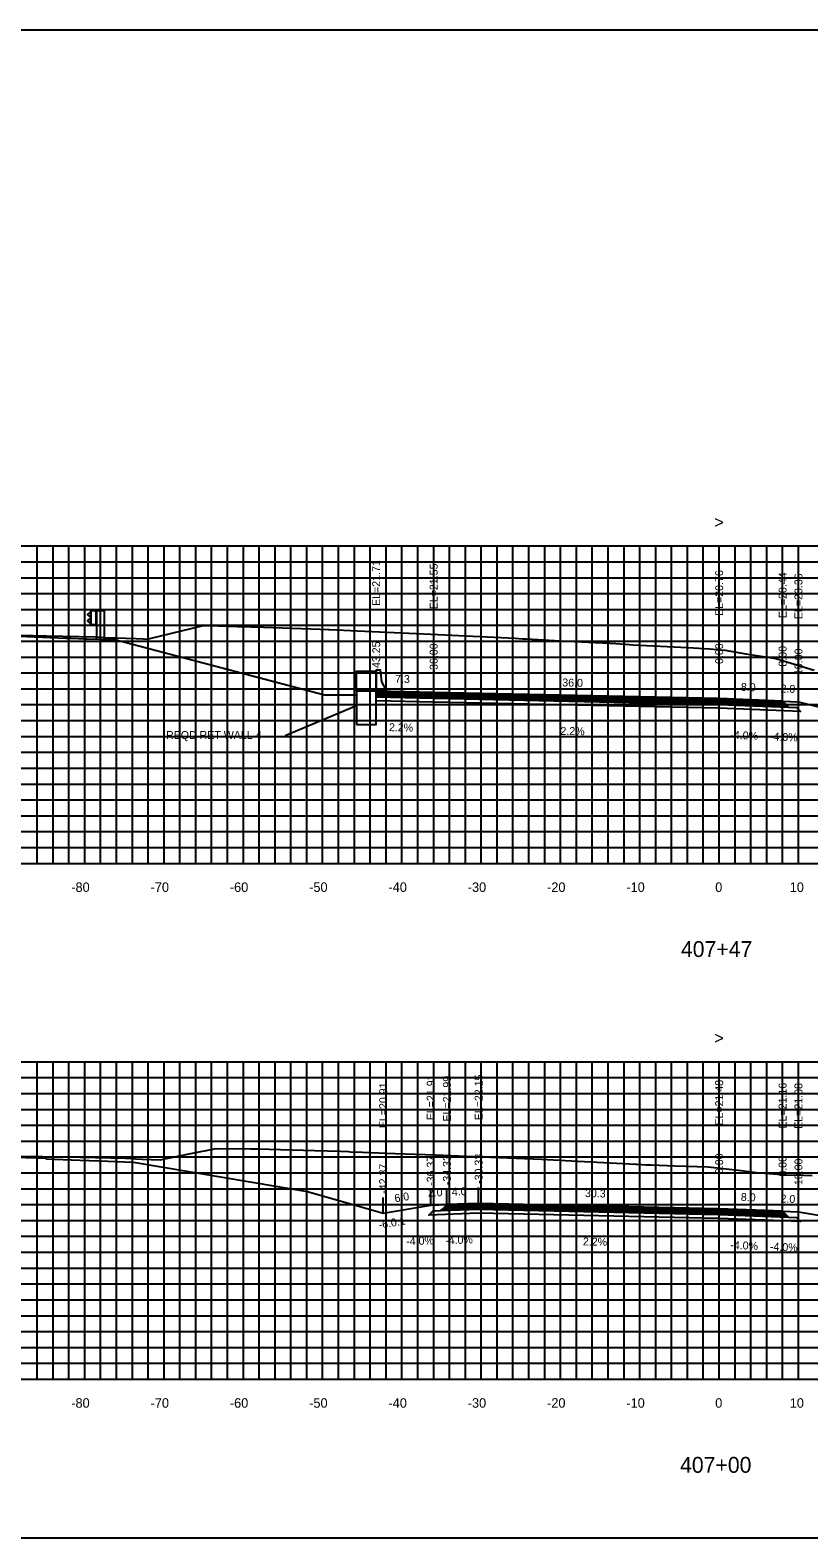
# Model space of a CAD drawing. Extents: x 1800976 to 1805104, y 250057 to 250580.
# Drawn here: x 1803224.1 to 1803322.3, y 250079.4 to 250269.4 of the extents above; entities that cross this region are included whole.
import ezdxf

# ---------------------------------------------------------------- set-up
doc = ezdxf.new("R2010")
doc.units = 0
for name, color, linetype in [('1', 7, 'Continuous'), ('10', 7, 'Continuous'), ('3', 7, 'Continuous'), ('4', 7, 'Continuous'), ('60', 7, 'Continuous'), ('BASE', 7, 'Continuous'), ('CL-CNST', 7, 'Continuous'), ('Default', 7, 'Continuous'), ('Level 1', 7, 'Continuous'), ('Level 62', 7, 'Continuous'), ('LOWER BINDER', 7, 'Continuous'), ('M-ROADS', 7, 'Continuous'), ('UPPER BINDER', 7, 'Continuous'), ('WEARING', 7, 'Continuous')]:
    doc.layers.add(name, color=color, linetype=linetype)

msp = doc.modelspace()

# ---------------------------------------------------------------- linework, layer by layer
for p, q in [((1803267.75, 250186.14), (1803267.75, 250188.14)), ((1803275, 250185.98), (1803275, 250187.98)), ((1803311, 250185.19), (1803311, 250187.19)), ((1803319, 250184.87), (1803319, 250186.87)), ((1803321, 250184.79), (1803321, 250186.79)), ((1803268.63, 250120.34), (1803268.63, 250122.34)), ((1803274.63, 250121.34), (1803274.63, 250123.34)), ((1803276.67, 250121.42), (1803276.67, 250123.42)), ((1803280.67, 250121.58), (1803280.67, 250123.58)), ((1803311, 250120.91), (1803311, 250122.91)), ((1803319, 250120.59), (1803319, 250122.59)), ((1803321, 250120.51), (1803321, 250122.51))]:
    msp.add_line(p, q)
msp.add_lwpolyline([(1803161, 250079.43), (1803461, 250079.43), (1803461, 250269.43), (1803161, 250269.43)], close=True)
at = {"layer": '3'}
msp.add_line((1803256.29, 250180.56), (1803265.25, 250184.33), dxfattribs=at)
at = {"layer": '60'}
for p, q in [((1803161, 250164.43), (1803461, 250164.43)), ((1803231, 250164.37), (1803231, 250164.43)), ((1803241, 250164.37), (1803241, 250164.43)), ((1803251, 250164.37), (1803251, 250164.43)), ((1803261, 250164.37), (1803261, 250164.43)), ((1803271, 250164.37), (1803271, 250164.43)), ((1803281, 250164.37), (1803281, 250164.43)), ((1803291, 250164.37), (1803291, 250164.43)), ((1803301, 250164.37), (1803301, 250164.43)), ((1803311, 250164.37), (1803311, 250164.43)), ((1803321, 250164.37), (1803321, 250164.43)), ((1803161, 250099.43), (1803461, 250099.43)), ((1803231, 250099.37), (1803231, 250099.43)), ((1803241, 250099.37), (1803241, 250099.43)), ((1803251, 250099.37), (1803251, 250099.43)), ((1803261, 250099.37), (1803261, 250099.43)), ((1803271, 250099.37), (1803271, 250099.43)), ((1803281, 250099.37), (1803281, 250099.43)), ((1803291, 250099.37), (1803291, 250099.43)), ((1803301, 250099.37), (1803301, 250099.43)), ((1803311, 250099.37), (1803311, 250099.43)), ((1803321, 250099.37), (1803321, 250099.43))]:
    msp.add_line(p, q, dxfattribs=at)
at = {"layer": 'BASE'}
for points in [[(1803267.75, 250185.42), (1803275, 250185.26), (1803311, 250184.47), (1803311, 250184.47), (1803319.75, 250184.12), (1803320.75, 250184.08), (1803321.27, 250183.56), (1803311, 250183.97), (1803311, 250183.97), (1803275, 250184.76), (1803267.75, 250184.92)], [(1803274.92, 250120.63), (1803275.92, 250120.67), (1803280.67, 250120.86), (1803311, 250120.19), (1803319.75, 250119.84), (1803320.75, 250119.8), (1803321.27, 250119.28), (1803311, 250119.69), (1803280.67, 250120.36), (1803274.4, 250120.11)]]:
    msp.add_lwpolyline(points, close=True, dxfattribs=at)
at = {"layer": 'CL-CNST'}
for points in [[(1803220.73, 250193.15), (1803228.63, 250192.82), (1803229.27, 250192.8), (1803231.09, 250192.72), (1803231.28, 250192.71), (1803234.81, 250192.64), (1803252.62, 250187.94), (1803261.25, 250185.66), (1803265.25, 250185.66)], [(1803234.81, 250192.64), (1803261.25, 250185.66), (1803265.25, 250185.66)], [(1803267.75, 250186.14), (1803275, 250185.98), (1803311, 250185.19), (1803319, 250184.87), (1803321, 250184.79), (1803345, 250178.79), (1803349, 250178.79), (1803361.72, 250181.97)], [(1803219.16, 250127.47), (1803225.05, 250127.33), (1803225.54, 250127.31), (1803226.05, 250127.29), (1803226.09, 250127.25), (1803226.13, 250127.21), (1803230.36, 250127.04), (1803235.12, 250126.84), (1803236.03, 250126.8), (1803237.14, 250126.76), (1803259.1, 250123.08), (1803268.63, 250120.34)], [(1803268.63, 250120.34), (1803274.63, 250121.34), (1803276.67, 250121.42), (1803280.67, 250121.58), (1803311, 250120.91), (1803319, 250120.59), (1803321, 250120.51), (1803351, 250115.51), (1803355, 250115.51), (1803368.47, 250118.88)]]:
    msp.add_lwpolyline(points, dxfattribs=at)
for points in [[(1803267.75, 250186.14), (1803265.25, 250186.14), (1803265.25, 250188.64), (1803267.75, 250188.64)], [(1803265.25, 250181.93), (1803267.75, 250181.93), (1803267.75, 250186.14), (1803265.25, 250186.14)]]:
    msp.add_lwpolyline(points, close=True, dxfattribs=at)
at = {"layer": 'Default'}
msp.add_line((1803267.75, 250186.14), (1803267.75, 250188.81), dxfattribs=at)
msp.add_lwpolyline([(1803267.75, 250188.81), (1803268.25, 250188.81), (1803268.43, 250187.31), (1803268.98, 250186.31), (1803269, 250186.14), (1803267.75, 250186.14)], dxfattribs=at)
at = {"layer": 'Level 1'}
for p, q in [((1803231.71, 250196.11), (1803231.35, 250195.81)), ((1803231.71, 250196.26), (1803231.71, 250194.51)), ((1803233.46, 250196.26), (1803231.71, 250196.26)), ((1803231.76, 250196.26), (1803231.76, 250194.51)), ((1803232.41, 250196.26), (1803232.41, 250194.51)), ((1803232.46, 250196.26), (1803232.46, 250192.74)), ((1803233.46, 250196.26), (1803233.46, 250192.7)), ((1803231.35, 250195.74), (1803231.71, 250195.46)), ((1803231.71, 250195.32), (1803231.35, 250195.02)), ((1803231.35, 250194.95), (1803231.71, 250194.66)), ((1803232.46, 250194.51), (1803231.71, 250194.51))]:
    msp.add_line(p, q, dxfattribs=at)
for centre in [(1803231.38, 250195.78), (1803231.38, 250194.98)]:
    msp.add_arc(centre, 0.05, 135, 226.6208, dxfattribs=at)
at = {"layer": 'Level 62'}
for p, q in [((1803161, 250204.43), (1803461, 250204.43)), ((1803225, 250164.43), (1803225, 250204.43)), ((1803227, 250164.43), (1803227, 250204.43)), ((1803229, 250164.43), (1803229, 250204.43)), ((1803231, 250164.43), (1803231, 250204.43)), ((1803233, 250164.43), (1803233, 250204.43)), ((1803235, 250164.43), (1803235, 250204.43)), ((1803237, 250164.43), (1803237, 250204.43)), ((1803239, 250164.43), (1803239, 250204.43)), ((1803241, 250164.43), (1803241, 250204.43)), ((1803243, 250164.43), (1803243, 250204.43)), ((1803245, 250164.43), (1803245, 250204.43)), ((1803247, 250164.43), (1803247, 250204.43)), ((1803249, 250164.43), (1803249, 250204.43)), ((1803251, 250164.43), (1803251, 250204.43)), ((1803253, 250164.43), (1803253, 250204.43)), ((1803255, 250164.43), (1803255, 250204.43)), ((1803257, 250164.43), (1803257, 250204.43)), ((1803259, 250164.43), (1803259, 250204.43)), ((1803261, 250164.43), (1803261, 250204.43)), ((1803263, 250164.43), (1803263, 250204.43)), ((1803265, 250164.43), (1803265, 250204.43)), ((1803267, 250164.43), (1803267, 250204.43)), ((1803269, 250164.43), (1803269, 250204.43)), ((1803271, 250164.43), (1803271, 250204.43)), ((1803273, 250164.43), (1803273, 250204.43)), ((1803275, 250164.43), (1803275, 250204.43)), ((1803277, 250164.43), (1803277, 250204.43)), ((1803279, 250164.43), (1803279, 250204.43)), ((1803281, 250164.43), (1803281, 250204.43)), ((1803283, 250164.43), (1803283, 250204.43)), ((1803285, 250164.43), (1803285, 250204.43)), ((1803287, 250164.43), (1803287, 250204.43)), ((1803289, 250164.43), (1803289, 250204.43)), ((1803291, 250164.43), (1803291, 250204.43)), ((1803293, 250164.43), (1803293, 250204.43)), ((1803295, 250164.43), (1803295, 250204.43)), ((1803297, 250164.43), (1803297, 250204.43)), ((1803299, 250164.43), (1803299, 250204.43)), ((1803301, 250164.43), (1803301, 250204.43)), ((1803303, 250164.43), (1803303, 250204.43)), ((1803305, 250164.43), (1803305, 250204.43)), ((1803307, 250164.43), (1803307, 250204.43)), ((1803309, 250164.43), (1803309, 250204.43)), ((1803311, 250164.43), (1803311, 250204.43)), ((1803313, 250164.43), (1803313, 250204.43)), ((1803315, 250164.43), (1803315, 250204.43)), ((1803317, 250164.43), (1803317, 250204.43)), ((1803319, 250164.43), (1803319, 250204.43)), ((1803321, 250164.43), (1803321, 250204.43)), ((1803161, 250202.43), (1803461, 250202.43)), ((1803161, 250200.43), (1803461, 250200.43)), ((1803161, 250198.43), (1803461, 250198.43)), ((1803161, 250196.43), (1803461, 250196.43)), ((1803161, 250194.43), (1803461, 250194.43)), ((1803161, 250192.43), (1803461, 250192.43)), ((1803161, 250190.43), (1803461, 250190.43)), ((1803161, 250188.43), (1803461, 250188.43)), ((1803161, 250186.43), (1803461, 250186.43)), ((1803161, 250184.43), (1803461, 250184.43)), ((1803161, 250182.43), (1803461, 250182.43)), ((1803161, 250180.43), (1803461, 250180.43)), ((1803161, 250178.43), (1803461, 250178.43)), ((1803161, 250176.43), (1803461, 250176.43)), ((1803161, 250174.43), (1803461, 250174.43)), ((1803161, 250172.43), (1803461, 250172.43)), ((1803161, 250170.43), (1803461, 250170.43)), ((1803161, 250168.43), (1803461, 250168.43)), ((1803161, 250166.43), (1803461, 250166.43)), ((1803161, 250164.43), (1803461, 250164.43)), ((1803161, 250139.43), (1803461, 250139.43)), ((1803225, 250099.43), (1803225, 250139.43)), ((1803227, 250099.43), (1803227, 250139.43)), ((1803229, 250099.43), (1803229, 250139.43)), ((1803231, 250099.43), (1803231, 250139.43)), ((1803233, 250099.43), (1803233, 250139.43)), ((1803235, 250099.43), (1803235, 250139.43)), ((1803237, 250099.43), (1803237, 250139.43)), ((1803239, 250099.43), (1803239, 250139.43)), ((1803241, 250099.43), (1803241, 250139.43)), ((1803243, 250099.43), (1803243, 250139.43)), ((1803245, 250099.43), (1803245, 250139.43)), ((1803247, 250099.43), (1803247, 250139.43)), ((1803249, 250099.43), (1803249, 250139.43)), ((1803251, 250099.43), (1803251, 250139.43)), ((1803253, 250099.43), (1803253, 250139.43)), ((1803255, 250099.43), (1803255, 250139.43)), ((1803257, 250099.43), (1803257, 250139.43)), ((1803259, 250099.43), (1803259, 250139.43)), ((1803261, 250099.43), (1803261, 250139.43)), ((1803263, 250099.43), (1803263, 250139.43)), ((1803265, 250099.43), (1803265, 250139.43)), ((1803267, 250099.43), (1803267, 250139.43)), ((1803269, 250099.43), (1803269, 250139.43)), ((1803271, 250099.43), (1803271, 250139.43)), ((1803273, 250099.43), (1803273, 250139.43)), ((1803275, 250099.43), (1803275, 250139.43)), ((1803277, 250099.43), (1803277, 250139.43)), ((1803279, 250099.43), (1803279, 250139.43)), ((1803281, 250099.43), (1803281, 250139.43)), ((1803283, 250099.43), (1803283, 250139.43)), ((1803285, 250099.43), (1803285, 250139.43)), ((1803287, 250099.43), (1803287, 250139.43)), ((1803289, 250099.43), (1803289, 250139.43)), ((1803291, 250099.43), (1803291, 250139.43)), ((1803293, 250099.43), (1803293, 250139.43)), ((1803295, 250099.43), (1803295, 250139.43)), ((1803297, 250099.43), (1803297, 250139.43)), ((1803299, 250099.43), (1803299, 250139.43)), ((1803301, 250099.43), (1803301, 250139.43)), ((1803303, 250099.43), (1803303, 250139.43)), ((1803305, 250099.43), (1803305, 250139.43)), ((1803307, 250099.43), (1803307, 250139.43)), ((1803309, 250099.43), (1803309, 250139.43)), ((1803311, 250099.43), (1803311, 250139.43)), ((1803313, 250099.43), (1803313, 250139.43)), ((1803315, 250099.43), (1803315, 250139.43)), ((1803317, 250099.43), (1803317, 250139.43)), ((1803319, 250099.43), (1803319, 250139.43)), ((1803321, 250099.43), (1803321, 250139.43)), ((1803161, 250137.43), (1803461, 250137.43)), ((1803161, 250135.43), (1803461, 250135.43)), ((1803161, 250133.43), (1803461, 250133.43)), ((1803161, 250131.43), (1803461, 250131.43)), ((1803161, 250129.43), (1803461, 250129.43)), ((1803161, 250127.43), (1803461, 250127.43)), ((1803161, 250125.43), (1803461, 250125.43)), ((1803161, 250123.43), (1803461, 250123.43)), ((1803161, 250121.43), (1803461, 250121.43)), ((1803161, 250119.43), (1803461, 250119.43)), ((1803161, 250117.43), (1803461, 250117.43)), ((1803161, 250115.43), (1803461, 250115.43)), ((1803161, 250113.43), (1803461, 250113.43)), ((1803161, 250111.43), (1803461, 250111.43)), ((1803161, 250109.43), (1803461, 250109.43)), ((1803161, 250107.43), (1803461, 250107.43)), ((1803161, 250105.43), (1803461, 250105.43)), ((1803161, 250103.43), (1803461, 250103.43)), ((1803161, 250101.43), (1803461, 250101.43)), ((1803161, 250099.43), (1803461, 250099.43))]:
    msp.add_line(p, q, dxfattribs=at)
at = {"layer": 'LOWER BINDER'}
for points in [[(1803275, 250185.64), (1803311, 250184.85), (1803311, 250184.85), (1803319.36, 250184.52), (1803319.55, 250184.32), (1803311, 250184.66), (1803311, 250184.66), (1803275, 250185.45), (1803267.75, 250185.61), (1803267.75, 250185.8)], [(1803275, 250185.45), (1803311, 250184.66), (1803311, 250184.66), (1803319.55, 250184.32), (1803319.75, 250184.12), (1803311, 250184.47), (1803311, 250184.47), (1803275, 250185.26), (1803267.75, 250185.42), (1803267.75, 250185.61)], [(1803280.67, 250121.05), (1803311, 250120.38), (1803319.55, 250120.04), (1803319.75, 250119.84), (1803311, 250120.19), (1803280.67, 250120.86), (1803275.92, 250120.67), (1803276.12, 250120.87)], [(1803280.67, 250121.24), (1803311, 250120.57), (1803319.36, 250120.24), (1803319.55, 250120.04), (1803311, 250120.38), (1803280.67, 250121.05), (1803276.12, 250120.87), (1803276.32, 250121.07)]]:
    msp.add_lwpolyline(points, close=True, dxfattribs=at)
at = {"layer": 'M-ROADS'}
for points in [[(1803220.86, 250193.23), (1803226.23, 250193.11), (1803232.31, 250192.96), (1803232.97, 250192.92), (1803233.55, 250192.9), (1803237.5, 250192.75), (1803238.35, 250192.72), (1803238.93, 250192.7), (1803239.21, 250192.77), (1803245.98, 250194.41), (1803246.32, 250194.4), (1803246.62, 250194.39), (1803250.26, 250194.3), (1803253.58, 250194.18), (1803260.67, 250193.94), (1803261.71, 250193.9), (1803261.92, 250193.89), (1803265.4, 250193.74), (1803274.62, 250193.32), (1803285.26, 250192.79), (1803286.19, 250192.74), (1803286.7, 250192.72), (1803290.97, 250192.49), (1803297.22, 250192.16), (1803297.96, 250192.12), (1803299.1, 250192.05), (1803299.21, 250192.04), (1803300.12, 250191.99), (1803307.06, 250191.64), (1803309.83, 250191.45), (1803311.15, 250191.35), (1803311.74, 250191.3), (1803314.36, 250190.85), (1803315.45, 250190.68), (1803318.15, 250190.26), (1803322.96, 250188.79)], [(1803213.6, 250127.67), (1803224.73, 250127.51), (1803225.67, 250127.49), (1803228.54, 250127.43), (1803234.23, 250127.31), (1803236.14, 250127.27), (1803237.07, 250127.22), (1803237.38, 250127.2), (1803238.25, 250127.15), (1803240.49, 250127.05), (1803244.17, 250127.83), (1803247.55, 250128.51), (1803251.88, 250128.47), (1803252.82, 250128.47), (1803260.02, 250128.25), (1803263.24, 250128.15), (1803264.27, 250128.1), (1803264.49, 250128.09), (1803266.03, 250128.03), (1803270.13, 250127.87), (1803275.23, 250127.68), (1803277.16, 250127.61), (1803281.12, 250127.45), (1803288.59, 250127.14), (1803292.37, 250126.95), (1803300.49, 250126.53), (1803300.67, 250126.51), (1803301.74, 250126.45), (1803302.45, 250126.43), (1803305.39, 250126.32), (1803309.6, 250126.17), (1803313.78, 250125.71), (1803315.72, 250125.48), (1803319.96, 250125.15), (1803320.71, 250125.19), (1803322.71, 250125.11)]]:
    msp.add_lwpolyline(points, dxfattribs=at)
at = {"layer": 'UPPER BINDER'}
for points in [[(1803311, 250184.85), (1803319.36, 250184.52), (1803319.16, 250184.71), (1803311, 250185.04), (1803311, 250185.04), (1803275, 250185.83), (1803267.75, 250185.99), (1803267.75, 250185.8), (1803275, 250185.64), (1803311, 250184.85)], [(1803319.36, 250120.24), (1803319.16, 250120.44), (1803311, 250120.76), (1803280.67, 250121.43), (1803276.52, 250121.26), (1803276.32, 250121.07), (1803280.67, 250121.24), (1803311, 250120.57)]]:
    msp.add_lwpolyline(points, close=True, dxfattribs=at)
at = {"layer": 'WEARING'}
for points in [[(1803311, 250185.04), (1803319.16, 250184.71), (1803319, 250184.87), (1803311, 250185.19), (1803311, 250185.19), (1803275, 250185.98), (1803267.75, 250186.14), (1803267.75, 250185.99), (1803275, 250185.83), (1803311, 250185.04)], [(1803319.16, 250120.44), (1803319, 250120.59), (1803311, 250120.91), (1803280.67, 250121.58), (1803276.67, 250121.42), (1803276.52, 250121.26), (1803280.67, 250121.43), (1803311, 250120.76)]]:
    msp.add_lwpolyline(points, close=True, dxfattribs=at)

# ---------------------------------------------------------------- texts
msp.add_text('-6.0:1', height=1, rotation=9.4623).set_placement((1803268.14, 250118.37))
at = {"layer": '1'}
for s, p in [('407+47', (1803306.18, 250152.63)), ('407+00', (1803306.07, 250087.63))]:
    msp.add_text(s, height=2, dxfattribs=at).set_placement(p)
at = {"layer": '10'}
for s, p in [('-80', (1803229.3, 250160.83)), ('-70', (1803239.3, 250160.83)), ('-60', (1803249.3, 250160.83)), ('-50', (1803259.3, 250160.83)), ('-40', (1803269.3, 250160.83)), ('-30', (1803279.3, 250160.83)), ('-20', (1803289.3, 250160.83)), ('-10', (1803299.3, 250160.83)), ('0', (1803310.5, 250160.83)), ('10', (1803319.9, 250160.83)), ('-80', (1803229.3, 250095.83)), ('-70', (1803239.3, 250095.83)), ('-60', (1803249.3, 250095.83)), ('-50', (1803259.3, 250095.83)), ('-40', (1803269.3, 250095.83)), ('-30', (1803279.3, 250095.83)), ('-20', (1803289.3, 250095.83)), ('-10', (1803299.3, 250095.83)), ('0', (1803310.5, 250095.83)), ('10', (1803319.9, 250095.83))]:
    msp.add_text(s, height=1.2, dxfattribs=at).set_placement(p)
at = {"layer": '3'}
for s, p in [('EL=21.71', (1803268.25, 250196.87)), ('EL=21.55', (1803275.5, 250196.45)), ('EL=20.76', (1803311.5, 250195.61)), ('EL=20.44', (1803319.5, 250195.34)), ('EL=20.36', (1803321.5, 250195.21)), ('-43.25', (1803268.25, 250188.6)), ('-36.00', (1803275.5, 250188.36)), ('0.00', (1803311.5, 250189.55)), ('8.00', (1803319.5, 250189.23)), ('10.00', (1803321.5, 250188.16)), ('EL=21.91', (1803275.13, 250132.06)), ('EL=21.99', (1803277.17, 250131.89)), ('EL=22.15', (1803281.17, 250132.05)), ('EL=21.48', (1803311.5, 250131.38)), ('EL=20.91', (1803269.13, 250131.06)), ('EL=21.16', (1803319.5, 250131.02)), ('EL=21.08', (1803321.5, 250130.98)), ('-36.37', (1803275.13, 250123.79)), ('-34.33', (1803277.17, 250123.88)), ('-30.33', (1803281.17, 250124.04)), ('0.00', (1803311.5, 250125.27)), ('8.00', (1803319.5, 250124.95)), ('-42.37', (1803269.13, 250122.79)), ('10.00', (1803321.5, 250123.88))]:
    msp.add_text(s, height=1, rotation=90, dxfattribs=at).set_placement(p)
msp.add_text('REQD RET WALL 4', height=1, dxfattribs=at).set_placement((1803241.25, 250180.1))
at = {"layer": '4'}
for s, rotation, p in [('7.3', 358.7397, (1803270.12, 250187.19)), ('36.0', 358.7397, (1803291.21, 250186.73)), ('8.0', 357.7094, (1803313.72, 250186.18)), ('2.0', 357.7094, (1803318.72, 250185.98)), ('2.2%', 358.7397, (1803269.35, 250181.1)), ('2.2%', 358.7397, (1803290.98, 250180.63)), ('-4.0%', 357.7094, (1803312.39, 250180.13)), ('-4.0%', 357.7094, (1803317.39, 250179.93)), ('4.0', 2.2906, (1803277.31, 250122.55)), ('6.0', 9.4623, (1803270.14, 250121.71)), ('2.0', 2.2906, (1803274.28, 250122.42)), ('30.3', 358.7397, (1803294.08, 250122.38)), ('8.0', 357.7094, (1803313.72, 250121.9)), ('2.0', 357.7094, (1803318.72, 250121.7)), ('-4.0%', 2.2906, (1803271.55, 250116.29)), ('-4.0%', 2.2906, (1803276.46, 250116.41)), ('2.2%', 358.7397, (1803293.81, 250116.29)), ('-4.0%', 357.7094, (1803312.39, 250115.85)), ('-4.0%', 357.7094, (1803317.39, 250115.65))]:
    msp.add_text(s, height=1, rotation=rotation, dxfattribs=at).set_placement(p)
at = {"layer": '60'}
for p in [(1803310.39, 250206.68), (1803310.39, 250141.68)]:
    msp.add_text('>', height=1.5, dxfattribs=at).set_placement(p)

doc.saveas('drawing.dxf')
